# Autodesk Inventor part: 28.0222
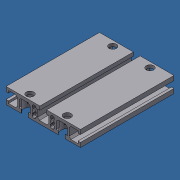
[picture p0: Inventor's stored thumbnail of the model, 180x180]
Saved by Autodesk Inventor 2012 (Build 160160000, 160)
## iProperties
Created: 2007-06
Part Number: 28.0222
Material: Aluminum-6061
Document SubType Name: Modeling
Designer: Andy Moles
Density: 2.71 g/cm^3
Description: L = 4.449", MILL TO 28.0222
Stock Number: 20.0995 PROFILE 90X19
Mass: 218.574 g
Surface Area: 552.03 cm^2
Volume: 80.6547 cm^3
Vendor: F
Author: Andy Moles
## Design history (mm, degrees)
sketch "Sketch1"
  geometry: L1 (18.4, -9.5)-(18.4, -5) reference; L2 (17.9, -5)-(15.7, -5) reference; L3 (15.7, -5)-(15.7, 3.5) reference; L4 (15.7, 3.5)-(18, 5.8) reference; L5 (18, 5.8)-(27, 5.8) reference; L6 (27, 5.8)-(29.3, 3.5) reference; L7 (29.3, 3.5)-(29.3, -5) reference; L8 (26.6, -5)-(26.6, -9.5) reference; L9 (45, -9.5)-(26.9, -9.5) reference; L10 (45, -4.1)-(45, -9.5) reference; L11 (45, -4.1)-(42, -4.1) reference; L12 (42, -4.6)-(42, -6.8) reference; L13 (42, -6.8)-(33.5, -6.8) reference; L14 (33.5, -6.8)-(31.2, -4.5) reference; L15 (31.2, -4.5)-(31.2, 4.5) reference; L16 (31.2, 4.5)-(33.5, 6.8) reference; L17 (33.5, 6.8)-(42, 6.8) reference; L18 (42, 4.1)-(45, 4.1) reference; L19 (45, 9.5)-(45, 4.1) reference; L20 (4.4, 9.5)-(45, 9.5) reference; L21 (4.1, 9.5)-(4.1, 5) reference; L22 (4.6, 5)-(6.8, 5) reference; L23 (6.8, 5)-(6.8, -3.5) reference; L24 (6.8, -3.5)-(4.5, -5.8) reference; L25 (4.5, -5.8)-(-4.5, -5.8) reference; L26 (-4.5, -5.8)-(-6.8, -3.5) reference; L27 (-6.8, -3.5)-(-6.8, 5) reference; L28 (-4.1, 5)-(-4.1, 9.5) reference; L29 (-45, 4.1)-(-45, 9.5) reference; L30 (-45, 4.1)-(-42, 4.1) reference; L31 (-42, 4.1)-(-42, 6.8) reference; L32 (-42, 6.8)-(-33.5, 6.8) reference; L33 (-33.5, 6.8)-(-31.2, 4.5) reference; L34 (-31.2, 4.5)-(-31.2, -4.5) reference; L35 (-31.2, -4.5)-(-33.5, -6.8) reference; L36 (-33.5, -6.8)-(-42, -6.8) reference; L37 (-42, -6.8)-(-42, -4.1) reference; L38 (-42, -4.1)-(-45, -4.1) reference; L39 (-45, -9.5)-(-45, -4.1) reference; L40 (-26.6, -9.5)-(-26.6, -5) reference; L41 (-29.3, -5)-(-29.3, 3.5) reference; L42 (-29.3, 3.5)-(-27, 5.8) reference; L43 (-27, 5.8)-(-18, 5.8) reference; L44 (-18, 5.8)-(-15.7, 3.5) reference; L45 (-15.7, 3.5)-(-15.7, -5) reference; L46 (-15.7, -5)-(-17.9, -5) reference; L47 (-18.4, -5)-(-18.4, -9.5) reference; L48 (-18.1, -9.5)-(-18.4, -9.5) reference; L49 (-26.6, -9.5)-(-45, -9.5) reference; L50 (-17.9, -5)-(-18.4, -5) reference; L51 (-26.6, -5)-(-29.3, -5) reference; L52 (-6.8, 5)-(-4.1, 5) reference; L53 (4.1, 5)-(4.6, 5) reference; L54 (-45, 9.5)-(-4.1, 9.5) reference; L55 (4.1, 9.5)-(4.4, 9.5) reference; L56 (29.3, -5)-(26.6, -5) reference; L57 (18.4, -5)-(17.9, -5) reference; L58 (26.9, -9.5)-(26.6, -9.5) reference; L59 (18.4, -9.5)-(-18.1, -9.5) reference; L60 (42, 6.8)-(42, 4.1) reference; L61 (42, -4.1)-(42, -4.6) reference; L62 (-9.354, -2.59)-(-8.993, -2.95); L63 (-10.7, -7)-(-11.3, -7); L64 (-8.7, -3.657)-(-8.7, -5)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; A1 r 2.5 centre (-11, 0) between (-9.333, -1.863) and (-9.333, 1.863); A2 r 1 centre (-9.7, -3.657) between (-8.7, -3.657) and (-8.993, -2.95); A3 r 2 centre (-10.7, -5) between (-10.7, -7) and (-8.7, -5); A4 r 0.5 centre (-9, -2.236) between (-9.333, -1.863) and (-9.354, -2.59); A5 r 1 centre (-12.3, -3.657) between (-13.007, -2.95) and (-13.3, -3.657); A6 r 2.5 centre (-11, 0) between (-12.667, 1.863) and (-12.667, -1.863); A7 r 2 centre (-11.3, -5) between (-13.3, -5) and (-11.3, -7); A8 r 0.5 centre (-13, -2.236) between (-12.646, -2.59) and (-12.667, -1.863); A9 r 0.5 centre (-13, 2.236) between (-12.667, 1.863) and (-12.646, 2.59); A10 r 2 centre (-11.3, 5) between (-11.3, 7) and (-13.3, 5); A11 r 0.5 centre (-9, 2.236) between (-9.354, 2.59) and (-9.333, 1.863); A12 r 1 centre (-9.7, 3.657) between (-8.993, 2.95) and (-8.7, 3.657); A13 r 2 centre (-10.7, 5) between (-8.7, 5) and (-10.7, 7); A14 r 1 centre (-12.3, 3.657) between (-13.3, 3.657) and (-13.007, 2.95); A15 r 1 centre (12.3, 3.657) between (13.007, 2.95) and (13.3, 3.657); A16 r 0.5 centre (13, 2.236) between (12.646, 2.59) and (12.667, 1.863); A17 r 2 centre (11.3, 5) between (13.3, 5) and (11.3, 7); A18 r 0.5 centre (9, 2.236) between (9.333, 1.863) and (9.354, 2.59); A19 r 1 centre (9.7, 3.657) between (8.7, 3.657) and (8.993, 2.95); A20 r 2 centre (10.7, 5) between (10.7, 7) and (8.7, 5); A21 r 1 centre (9.7, -3.657) between (8.993, -2.95) and (8.7, -3.657); A22 r 2.5 centre (11, 0) between (9.333, 1.863) and (9.333, -1.863); A23 r 0.5 centre (9, -2.236) between (9.354, -2.59) and (9.333, -1.863); A24 r 2 centre (10.7, -5) between (8.7, -5) and (10.7, -7); A25 r 2.5 centre (11, 0) between (12.667, -1.863) and (12.667, 1.863); A26 r 0.5 centre (13, -2.236) between (12.667, -1.863) and (12.646, -2.59); A27 r 1 centre (12.3, -3.657) between (13.3, -3.657) and (13.007, -2.95); A28 r 2 centre (11.3, -5) between (11.3, -7) and (13.3, -5)
  constraints: 162 end point, 56 point on circle, 28 centre point, 28 horizontal, 23 vertical, 71 other
extrude "Extrusion1" new body sketch "Sketch1" stored distance "d0" = 113; taper "d1" = 0 deg
sketch "Sketch2"
  geometry: L1 (0, -113)-(36.8, -113) reference; L2 (63.4, -113)-(63.4, 0) reference; L3 (36.8, 0)-(0, 0) reference; 5 further points
  constraints: 2 horizontal alignment, 2 vertical alignment
  dimensions: "d2" = 113 distance of L1.end L3.start (derived); "d5" = 22.5 distance from line of point (40.9, -6.5) L2; "d6" = 67.5 distance from line of point (-4.1, -6.5) L2; "d14" = 6.5 distance from line of point (40.9, -6.5) L3; "d15" = 6.5 distance from line of point (40.9, -106.5) L1
hole "Hole1" sketch "Sketch2" at (40.9, -6.5), (-4.1, -6.5), (-4.1, -106.5), (40.9, -106.5) diameter "d7" = 9; stored, may be unused: countersink angle "d11" = 90 deg, drill point angle "d13" = 118 deg; dims "d8" = 6, "d9" = 15, "d10" = 15.3, "d12" = 8
body "Solid1"
